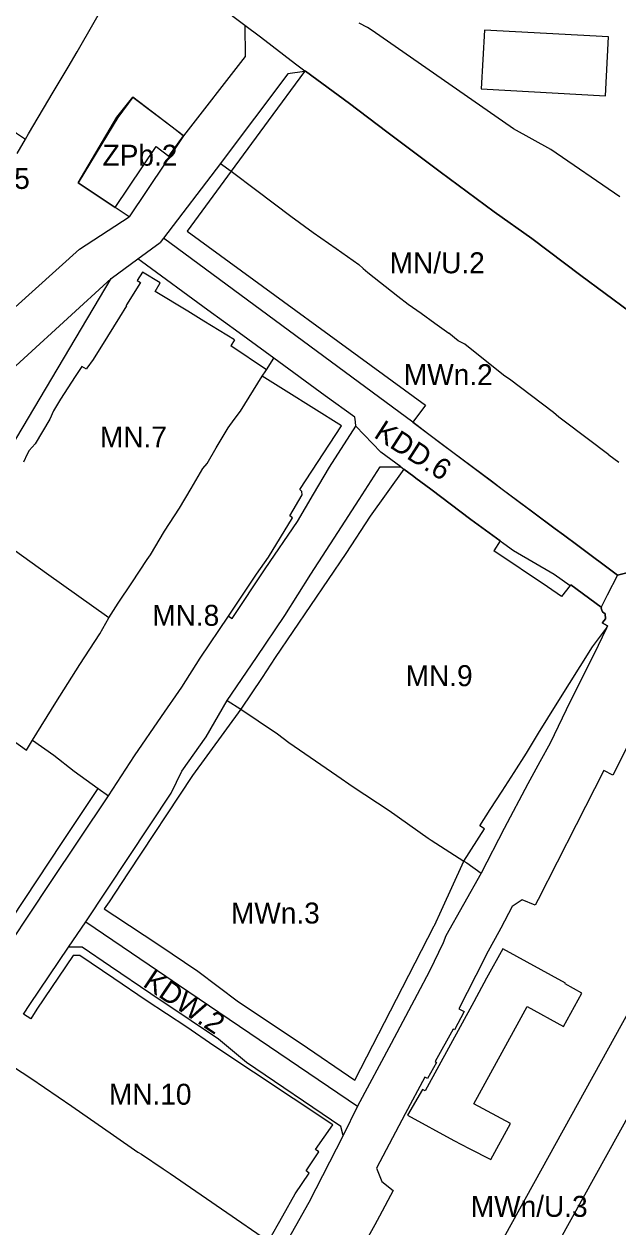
# Model space of a CAD drawing. Extents: x 7425067 to 7426806, y 5549054 to 5550619.
# Drawn here: x 7425656.7 to 7425798.3, y 5549976.3 to 5550263.3 of the extents above; entities that cross this region are included whole.
import ezdxf

# ---------------------------------------------------------------- set-up
doc = ezdxf.new("R2010")
doc.units = 0
for name, color, linetype in [('LIN_Linia Zabudowy Nieprzekraczalna', 7, 'Continuous'), ('LIN_linia zabudowy obowiązująca', 7, 'Continuous'), ('LIN_linie_rozgraniczajace', 7, 'Continuous'), ('TXT_Oznaczenia_przeznaczen', 7, 'Continuous')]:
    doc.layers.add(name, color=color, linetype=linetype)

msp = doc.modelspace()

# ---------------------------------------------------------------- linework, layer by layer
at = {"layer": 'LIN_Linia Zabudowy Nieprzekraczalna'}
for points in [[(7425723.6504, 5550252.1479), (7425723.5322, 5550251.9866), (7425714.88, 5550240.18), (7425706.0572, 5550228.1406), (7425695.5679, 5550213.8271)], [(7425734.29, 5550244.29), (7425723.8133, 5550252.0277), (7425723.6504, 5550252.1479)], [(7425643.3462, 5550245.0982), (7425649, 5550241.7939), (7425649.9122, 5550241.0902), (7425648.76, 5550239.42), (7425652.55, 5550236.62), (7425653.6759, 5550238.1865), (7425654.8959, 5550237.2454), (7425657.0714, 5550235.8304)], [(7425743.15, 5550237.6), (7425734.29, 5550244.29)], [(7425755.89, 5550227.99), (7425743.15, 5550237.6)], [(7425768.78, 5550218.5), (7425755.89, 5550227.99)], [(7425777.76, 5550212.12), (7425768.78, 5550218.5)], [(7425695.5679, 5550213.8271), (7425752.4319, 5550172.3811)], [(7425789.46, 5550203.32), (7425777.76, 5550212.12)], [(7425706.8644, 5550187.9015), (7425699.57, 5550192.42), (7425695.72, 5550194.78), (7425687.9499, 5550199.5099), (7425689.17, 5550201.51), (7425684.95, 5550204.08), (7425683.7, 5550202.1), (7425684.5, 5550201.61), (7425681.13, 5550196.26), (7425681.05, 5550196.08), (7425681.12, 5550196.04), (7425679.5, 5550193.35), (7425676.58, 5550188.74), (7425673.17, 5550183.27), (7425671.68, 5550181.22), (7425671.62, 5550180.97), (7425670.46, 5550181.59), (7425670.16, 5550181.12), (7425668.88, 5550179.16), (7425665.37, 5550173.81), (7425664.22, 5550171.78), (7425663.75, 5550171.01), (7425662.83, 5550169.03), (7425659.36, 5550163.15), (7425657.94, 5550161.51), (7425657.44, 5550160.64), (7425656.55, 5550158.74)], [(7425801.06, 5550194.69), (7425789.46, 5550203.32)], [(7425706.8644, 5550187.9015), (7425705.9808, 5550186.4867)], [(7425713.4587, 5550179.2567), (7425714.3429, 5550180.5794), (7425714.4852, 5550180.8012), (7425705.9808, 5550186.4867)], [(7425732.4116, 5550167.4042), (7425719.21, 5550175.66), (7425713.4971, 5550179.2327), (7425713.4587, 5550179.2567)], [(7425752.4319, 5550172.3811), (7425749.37, 5550168.28)], [(7425705.41, 5550121.99), (7425712.1, 5550132.04), (7425714.96, 5550136.08), (7425720.73, 5550145.49), (7425720.05, 5550145.93), (7425723.04, 5550150.95), (7425722.94, 5550151.72), (7425722.43, 5550152.21), (7425732.4116, 5550167.4042)], [(7425749.37, 5550168.28), (7425768.13, 5550154.2), (7425783.3417, 5550142.8577), (7425785.27, 5550141.43), (7425788.73, 5550138.84)], [(7425770.22, 5550139.98), (7425763.24, 5550145.09), (7425753.66, 5550152.34), (7425750.1, 5550154.975), (7425749.6492, 5550155.3088), (7425747.2699, 5550157.0699), (7425739.22, 5550145.88), (7425733.43, 5550136.96), (7425716.59, 5550112.19), (7425713.48, 5550107.41), (7425708.37, 5550099.83)], [(7425788.73, 5550138.84), (7425798.17, 5550131.83), (7425800.74, 5550132.42), (7425807.33, 5550144.23)], [(7425770.22, 5550139.98), (7425768.6957, 5550137.5981)], [(7425786.8862, 5550129.3024), (7425784.84, 5550126.74), (7425781.45, 5550129.02), (7425768.6957, 5550137.5981)], [(7425783.79, 5550101.26), (7425792.24, 5550114.66), (7425795.54, 5550119.18), (7425795.77, 5550119.74), (7425794.51, 5550120.43), (7425794.65, 5550120.6), (7425795.31, 5550121.41), (7425795.25, 5550122.55), (7425794.6136, 5550123.0868), (7425794.3085, 5550123.8074), (7425794.47, 5550124.03), (7425794.2765, 5550124.1713), (7425787.02, 5550129.47), (7425786.8862, 5550129.3024)], [(7425676.81, 5550079.14), (7425683.08, 5550088.67), (7425689.48, 5550098.09), (7425694.29, 5550105.04), (7425698.72, 5550111.96), (7425705.41, 5550121.99)], [(7425708.37, 5550099.83), (7425696.8865, 5550083.998), (7425681.5412, 5550060.8203)], [(7425765.3724, 5550071.9813), (7425767.85, 5550075.92), (7425770.7, 5550080.3), (7425773.57, 5550084.73), (7425776.44, 5550089.34), (7425779.37, 5550094.1), (7425783.79, 5550101.26)], [(7425665.8055, 5550068.0549), (7425674.3852, 5550080.8809), (7425676.81, 5550079.14)], [(7425761.54, 5550063.58), (7425766.5, 5550071.26), (7425765.3724, 5550071.9813)], [(7425641.7634, 5550031.6816), (7425665.8055, 5550068.0549)], [(7425754.4765, 5550048.1318), (7425754.5355, 5550048.2464), (7425756.2124, 5550051.8896), (7425761.54, 5550063.58)], [(7425681.5412, 5550060.8203), (7425681.5256, 5550060.7966), (7425676.9637, 5550053.8685), (7425675.8274, 5550052.204), (7425678.3491, 5550050.5184), (7425688.8582, 5550043.5856)], [(7425735.5402, 5550011.2981), (7425746.9041, 5550033.4238), (7425754.4765, 5550048.1318)], [(7425688.8582, 5550043.5856), (7425698.1686, 5550037.3516), (7425707.8545, 5550030.0447), (7425722.7668, 5550020.0965), (7425735.5402, 5550011.2981)], [(7425669.979, 5550041.0643), (7425668.3823, 5550041.0497), (7425659.7796, 5550028.2387), (7425658.2986, 5550025.9526), (7425656.62, 5550027.04)], [(7425730.2813, 5550000.6279), (7425701.99, 5550019.54), (7425695.54, 5550023.97), (7425685.81, 5550030.33), (7425678.11, 5550035.55), (7425669.979, 5550041.0643)], [(7425688.8399, 5549929.4585), (7425691.2009, 5549933.3935), (7425702.6055, 5549951.9648), (7425702.86, 5549951.8), (7425709.48, 5549963.44), (7425710.7848, 5549965.653), (7425714.2539, 5549971.5633), (7425714.9902, 5549972.8797), (7425718.3675, 5549978.9183), (7425721.36, 5549984.23), (7425724.68, 5549989.11), (7425723.92, 5549989.66), (7425727.01, 5549994.19), (7425726.17, 5549994.77), (7425730.2813, 5550000.6279)]]:
    msp.add_lwpolyline(points, dxfattribs=at)
at = {"layer": 'LIN_linia zabudowy obowiązująca'}
for points in [[(7425766.4505, 5550261.8233), (7425765.6807, 5550247.8164), (7425795.28, 5550246.18), (7425796.05, 5550260.2), (7425766.4505, 5550261.8233)], [(7425678.4113, 5550219.483), (7425688.2005, 5550234.0314), (7425691.22, 5550231.75), (7425694.75, 5550236.6), (7425682.62, 5550245.86), (7425679.03, 5550240.96), (7425669.6, 5550225.38), (7425678.4113, 5550219.483)], [(7425827.66, 5550076.24), (7425771.07, 5549973.79)], [(7425771.07, 5549973.79), (7425781.44, 5549967.75), (7425838.25, 5550070.38), (7425827.66, 5550076.24)], [(7425770.81, 5550042.66), (7425766.98, 5550035.63), (7425763.9298, 5550030.0314), (7425752.3372, 5550008.753)], [(7425789.7, 5550032.1), (7425785.68, 5550034.31), (7425785.78, 5550034.49), (7425770.81, 5550042.66)], [(7425767.9516, 5549992.377), (7425772.6827, 5550001.0181), (7425763.9256, 5550005.7011), (7425774.7312, 5550025.4086), (7425776.64, 5550028.89), (7425785.32, 5550024.1), (7425789.7, 5550032.1)], [(7425752.3372, 5550008.753), (7425751.67, 5550009.12), (7425748.1216, 5550002.9402)], [(7425748.1216, 5550002.9402), (7425759.1331, 5549996.9604), (7425762.8, 5549994.98), (7425767.9516, 5549992.377)]]:
    msp.add_lwpolyline(points, dxfattribs=at)
at = {"layer": 'LIN_linie_rozgraniczajace'}
for points in [[(7425669.35, 5550256.66), (7425681.8566, 5550278.5552), (7425683.71, 5550281.8)], [(7425698.09, 5550271.56), (7425709.34, 5550263.01)], [(7425738.59, 5550262.44), (7425736.62, 5550263.51)], [(7425709.34, 5550263.01), (7425709.449, 5550255.5422)], [(7425709.34, 5550263.01), (7425713.11, 5550260.26)], [(7425713.11, 5550260.26), (7425721.4, 5550253.81)], [(7425739.71, 5550261.77), (7425738.59, 5550262.44)], [(7425773.39, 5550238.26), (7425739.71, 5550261.77)], [(7425667.19, 5550252.99), (7425669.35, 5550256.66)], [(7425709.449, 5550255.5422), (7425694.75, 5550236.6)], [(7425663.67, 5550247.03), (7425667.19, 5550252.99)], [(7425723.8133, 5550252.0277), (7425723.5322, 5550251.9866), (7425719.5973, 5550251.4119)], [(7425721.4, 5550253.81), (7425723.6504, 5550252.1479), (7425723.8133, 5550252.0277), (7425734.29, 5550244.29)], [(7425719.5973, 5550251.4119), (7425703.69, 5550230.25)], [(7425657.79, 5550237.05), (7425663.67, 5550247.03)], [(7425681.73, 5550217.25), (7425678.4113, 5550219.483), (7425669.6, 5550225.38), (7425678.82, 5550241.04), (7425682.62, 5550245.86), (7425692.37, 5550238.55), (7425694.75, 5550236.6)], [(7425734.29, 5550244.29), (7425743.15, 5550237.6)], [(7425743.15, 5550237.6), (7425755.89, 5550227.99)], [(7425782.29, 5550233.35), (7425773.39, 5550238.26)], [(7425655.04, 5550232.38), (7425657.0714, 5550235.8304), (7425657.79, 5550237.05)], [(7425694.75, 5550236.6), (7425681.73, 5550217.25)], [(7425798.69, 5550222.07), (7425782.29, 5550233.35)], [(7425703.5262, 5550230.0342), (7425689.9613, 5550212.1623)], [(7425703.69, 5550230.25), (7425703.5262, 5550230.0342)], [(7425703.5262, 5550230.0342), (7425706.0572, 5550228.1406), (7425712.18, 5550223.56)], [(7425755.89, 5550227.99), (7425768.78, 5550218.5)], [(7425712.18, 5550223.56), (7425720.285, 5550217.44)], [(7425669.9439, 5550209.5582), (7425681.73, 5550217.25)], [(7425720.285, 5550217.44), (7425725.65, 5550213.56)], [(7425768.78, 5550218.5), (7425777.76, 5550212.12)], [(7425689.9613, 5550212.1623), (7425689.1831, 5550211.137)], [(7425734.85, 5550179.05), (7425689.9613, 5550212.1623)], [(7425725.65, 5550213.56), (7425731.09, 5550209.725)], [(7425777.76, 5550212.12), (7425789.46, 5550203.32)], [(7425638.3977, 5550181.1426), (7425669.9439, 5550209.5582)], [(7425683.8442, 5550207.2287), (7425689.1831, 5550211.137)], [(7425731.09, 5550209.725), (7425736.53, 5550205.89)], [(7425677.4704, 5550202.5629), (7425683.8442, 5550207.2287)], [(7425684.68, 5550206.6), (7425683.8442, 5550207.2287)], [(7425700.56, 5550195.02), (7425684.68, 5550206.6)], [(7425736.53, 5550205.89), (7425737.58, 5550204.93)], [(7425737.58, 5550204.93), (7425738.63, 5550203.97)], [(7425738.63, 5550203.97), (7425745.8, 5550198.34)], [(7425789.46, 5550203.32), (7425801.06, 5550194.69)], [(7425625.3385, 5550154.8249), (7425677.4704, 5550202.5629)], [(7425643.57, 5550145.47), (7425677.4704, 5550202.5629)], [(7425745.8, 5550198.34), (7425748.3, 5550196.42)], [(7425707.95, 5550189.64), (7425700.56, 5550195.02)], [(7425748.3, 5550196.42), (7425751.35, 5550194.29)], [(7425751.35, 5550194.29), (7425754.65, 5550191.895)], [(7425754.65, 5550191.895), (7425757.95, 5550189.5)], [(7425716.24, 5550183.6), (7425707.95, 5550189.64)], [(7425760.17, 5550187.7), (7425757.95, 5550189.5)], [(7425761.77, 5550186.9), (7425760.17, 5550187.7)], [(7425769.83, 5550180.47), (7425761.77, 5550186.9)], [(7425708.27, 5550170.91), (7425713.4971, 5550179.2327), (7425714.3429, 5550180.5794), (7425714.4852, 5550180.8012), (7425716.24, 5550183.6)], [(7425728.525, 5550174.62), (7425716.24, 5550183.6)], [(7425771.35, 5550179.29), (7425769.83, 5550180.47)], [(7425744.57, 5550171.88), (7425734.85, 5550179.05)], [(7425772.4, 5550178.54), (7425771.35, 5550179.29)], [(7425782.94, 5550170.62), (7425772.4, 5550178.54)], [(7425735.5636, 5550169.4749), (7425728.525, 5550174.62)], [(7425749.37, 5550168.28), (7425744.57, 5550171.88)], [(7425705.39, 5550166.91), (7425706.83, 5550168.91)], [(7425706.83, 5550168.91), (7425708.27, 5550170.91)], [(7425735.6875, 5550168.3768), (7425735.5636, 5550169.4749)], [(7425784.16, 5550169.51), (7425782.94, 5550170.62)], [(7425785.42, 5550168.57), (7425784.16, 5550169.51)], [(7425796.12, 5550160.52), (7425785.42, 5550168.57)], [(7425703.935, 5550164.545), (7425705.39, 5550166.91)], [(7425729.56, 5550157.6), (7425735.8, 5550167.38)], [(7425735.8, 5550167.38), (7425735.6875, 5550168.3768)], [(7425741.74, 5550161.16), (7425735.8, 5550167.38)], [(7425752.905, 5550165.585), (7425749.37, 5550168.28)], [(7425756.44, 5550162.89), (7425752.905, 5550165.585)], [(7425702.48, 5550162.18), (7425703.935, 5550164.545)], [(7425768.13, 5550154.2), (7425756.44, 5550162.89)], [(7425700.36, 5550158.44), (7425702.48, 5550162.18)], [(7425746.54, 5550157.61), (7425741.74, 5550161.16)], [(7425796.12, 5550160.52), (7425798.48, 5550158.74)], [(7425696.58, 5550152.46), (7425699.36, 5550157.27)], [(7425699.36, 5550157.27), (7425700.36, 5550158.44)], [(7425725.715, 5550151.12), (7425729.56, 5550157.6)], [(7425736.565, 5550149.815), (7425741.6, 5550157.66)], [(7425741.6, 5550157.66), (7425746.54, 5550157.61)], [(7425746.54, 5550157.61), (7425747.2699, 5550157.0699), (7425749.6492, 5550155.3088), (7425750.1, 5550154.975)], [(7425750.1, 5550154.975), (7425753.66, 5550152.34)], [(7425770.71, 5550152.21), (7425768.13, 5550154.2)], [(7425693.74, 5550147.79), (7425696.58, 5550152.46)], [(7425753.66, 5550152.34), (7425763.24, 5550145.09)], [(7425777.99, 5550146.82), (7425770.71, 5550152.21)], [(7425721.87, 5550144.64), (7425725.715, 5550151.12)], [(7425731.53, 5550141.97), (7425736.565, 5550149.815)], [(7425690.175, 5550142.3), (7425693.74, 5550147.79)], [(7425785.27, 5550141.43), (7425783.3417, 5550142.8577), (7425777.99, 5550146.82)], [(7425714.2, 5550133.34), (7425721.87, 5550144.64)], [(7425763.24, 5550145.09), (7425770.22, 5550139.98)], [(7425662.1, 5550132.23), (7425648.66, 5550141.83)], [(7425686.87, 5550136.67), (7425690.175, 5550142.3)], [(7425725.1, 5550132.01), (7425731.53, 5550141.97)], [(7425770.22, 5550139.98), (7425771.1, 5550139.35)], [(7425788.73, 5550138.84), (7425785.27, 5550141.43)], [(7425771.1, 5550139.35), (7425773.41, 5550137.69)], [(7425773.41, 5550137.69), (7425783.04, 5550132.04)], [(7425798.17, 5550131.83), (7425788.73, 5550138.84)], [(7425682.39, 5550129.95), (7425686.02, 5550135.5)], [(7425686.02, 5550135.5), (7425686.87, 5550136.67)], [(7425676.92, 5550121.64), (7425662.1, 5550132.23)], [(7425706.31, 5550121.49), (7425714.2, 5550133.34)], [(7425718.9, 5550122.19), (7425725.1, 5550132.01)], [(7425783.04, 5550132.04), (7425786.8862, 5550129.3024)], [(7425798.17, 5550131.83), (7425795.73, 5550127.04)], [(7425800.74, 5550132.42), (7425798.17, 5550131.83)], [(7425679.14, 5550125.14), (7425682.39, 5550129.95)], [(7425786.8862, 5550129.3024), (7425787.02, 5550129.47), (7425794.2765, 5550124.1713), (7425794.47, 5550124.03), (7425794.3085, 5550123.8074), (7425794.6136, 5550123.0868), (7425795.25, 5550122.55), (7425795.31, 5550121.41), (7425794.65, 5550120.6), (7425794.51, 5550120.43)], [(7425795.73, 5550127.04), (7425794.2765, 5550124.1713)], [(7425676.92, 5550121.64), (7425679.14, 5550125.14)], [(7425674.77, 5550117.84), (7425676.92, 5550121.64)], [(7425698.72, 5550111.96), (7425705.41, 5550121.99)], [(7425705.41, 5550121.99), (7425706.31, 5550121.49)], [(7425712.09, 5550112.16), (7425718.9, 5550122.19)], [(7425795.77, 5550119.74), (7425795.54, 5550119.18), (7425792.56, 5550112.88)], [(7425794.51, 5550120.43), (7425795.77, 5550119.74)], [(7425669.98, 5550110.47), (7425674.77, 5550117.84)], [(7425694.29, 5550105.04), (7425698.72, 5550111.96)], [(7425705.1471, 5550101.8757), (7425712.09, 5550112.16)], [(7425792.56, 5550112.88), (7425786.89, 5550101.63)], [(7425664.32, 5550101.4), (7425669.98, 5550110.47)], [(7425689.48, 5550098.09), (7425694.29, 5550105.04)], [(7425658.73, 5550092.43), (7425664.32, 5550101.4)], [(7425700.1, 5550093.245), (7425705.1471, 5550101.8757)], [(7425705.1471, 5550101.8757), (7425708.37, 5550099.83)], [(7425708.37, 5550099.83), (7425712.48, 5550097.06)], [(7425786.89, 5550101.63), (7425782.12, 5550091.72)], [(7425646.98, 5550097.47), (7425657.32, 5550090.05)], [(7425683.08, 5550088.67), (7425689.48, 5550098.09)], [(7425712.48, 5550097.06), (7425717.11, 5550093.93)], [(7425717.11, 5550093.93), (7425719.86, 5550091.88)], [(7425657.32, 5550090.05), (7425658.025, 5550091.24)], [(7425658.025, 5550091.24), (7425658.73, 5550092.43)], [(7425658.73, 5550092.43), (7425663.8, 5550088.89)], [(7425694.34, 5550085.07), (7425700.1, 5550093.245)], [(7425719.86, 5550091.88), (7425731.3, 5550084.03)], [(7425782.12, 5550091.72), (7425779.62, 5550087.25)], [(7425800.705, 5550091.3047), (7425797.03, 5550084.0798)], [(7425663.8, 5550088.89), (7425668.62, 5550085.02)], [(7425676.81, 5550079.14), (7425683.08, 5550088.67)], [(7425779.62, 5550087.25), (7425776.82, 5550082.01)], [(7425668.62, 5550085.02), (7425674.3852, 5550080.8809), (7425676.81, 5550079.14)], [(7425691.78, 5550079.79), (7425694.34, 5550085.07)], [(7425731.3, 5550084.03), (7425735.16, 5550081.3)], [(7425794.9029, 5550085.1617), (7425788.32, 5550072.22)], [(7425797.03, 5550084.0798), (7425794.9029, 5550085.1617)], [(7425681.605, 5550064.44), (7425691.78, 5550079.79)], [(7425735.16, 5550081.3), (7425743.76, 5550075.68)], [(7425776.82, 5550082.01), (7425771.15, 5550071.35)], [(7425662.84, 5550058.21), (7425676.81, 5550079.14)], [(7425743.76, 5550075.68), (7425753.07, 5550069.05)], [(7425771.15, 5550071.35), (7425765.67, 5550060.69)], [(7425788.32, 5550072.22), (7425779.24, 5550054.4)], [(7425753.07, 5550069.05), (7425753.79, 5550068.57)], [(7425753.79, 5550068.57), (7425761.54, 5550063.58)], [(7425671.43, 5550049.09), (7425681.605, 5550064.44)], [(7425761.54, 5550063.58), (7425762.23, 5550063.14)], [(7425762.23, 5550063.14), (7425765.67, 5550060.69)], [(7425765.67, 5550060.69), (7425757.27, 5550045.74)], [(7425648.87, 5550037.28), (7425662.84, 5550058.21)], [(7425775.46, 5550054.32), (7425773.025, 5550052.78)], [(7425778.57, 5550053.06), (7425775.46, 5550054.32)], [(7425779.24, 5550054.4), (7425778.57, 5550053.06)], [(7425773.025, 5550052.78), (7425770.36, 5550047.58)], [(7425667.31, 5550043.04), (7425671.43, 5550049.09)], [(7425671.43, 5550049.09), (7425686.53, 5550038.81)], [(7425757.27, 5550045.74), (7425756.58, 5550044.1)], [(7425769.89, 5550046.72), (7425767.36, 5550042.09)], [(7425770.36, 5550047.58), (7425769.89, 5550046.72)], [(7425658.11, 5550029.34), (7425667.31, 5550043.04)], [(7425670.59, 5550043.07), (7425667.31, 5550043.04)], [(7425677.35, 5550038.44), (7425670.59, 5550043.07)], [(7425756.58, 5550044.1), (7425753.37, 5550037.35)], [(7425767.36, 5550042.09), (7425764.41, 5550036.28)], [(7425686.92, 5550031.89), (7425677.35, 5550038.44)], [(7425686.53, 5550038.81), (7425690.49, 5550036.11)], [(7425753.37, 5550037.35), (7425750.415, 5550031.78)], [(7425690.49, 5550036.11), (7425693.55, 5550034.03)], [(7425693.55, 5550034.03), (7425710.56, 5550022.52)], [(7425764.41, 5550036.28), (7425762.33, 5550032.22)], [(7425696.55, 5550025.46), (7425686.92, 5550031.89)], [(7425750.415, 5550031.78), (7425744.215, 5550020.055)], [(7425762.33, 5550032.22), (7425760.36, 5550028.35)], [(7425656.62, 5550027.04), (7425658.11, 5550029.34)], [(7425760.36, 5550028.35), (7425761.61, 5550027.68)], [(7425703.04, 5550021.12), (7425696.55, 5550025.46)], [(7425761.61, 5550027.68), (7425759.32, 5550023.31)], [(7425710.56, 5550022.52), (7425736.18, 5550005.13)], [(7425758.97, 5550023.49), (7425754.69, 5550015.8)], [(7425759.32, 5550023.31), (7425758.97, 5550023.49)], [(7425709.75, 5550015.56), (7425703.04, 5550021.12)], [(7425744.215, 5550020.055), (7425736.18, 5550005.13)], [(7425649.98, 5550017.22), (7425658.32, 5550011.79)], [(7425732.25, 5550000.28), (7425709.75, 5550015.56)], [(7425755.04, 5550015.51), (7425752.87, 5550011.74)], [(7425754.69, 5550015.8), (7425755.04, 5550015.51)], [(7425658.32, 5550011.79), (7425668.12, 5550005.08)], [(7425752.235, 5550012.025), (7425747.545, 5550003.255)], [(7425752.87, 5550011.74), (7425752.235, 5550012.025)], [(7425668.12, 5550005.08), (7425678.07, 5549998.16)], [(7425736.18, 5550005.13), (7425732.79, 5549998.15)], [(7425747.545, 5550003.255), (7425740.7378, 5549990.3615)], [(7425732.79, 5549998.15), (7425732.25, 5550000.28)], [(7425678.07, 5549998.16), (7425683.87, 5549994.18)], [(7425732.79, 5549998.15), (7425724.58, 5549982.13)], [(7425683.87, 5549994.18), (7425684.68, 5549993.63)], [(7425684.68, 5549993.63), (7425689.87, 5549990.15)], [(7425689.87, 5549990.15), (7425691.53, 5549989.04)], [(7425691.53, 5549989.04), (7425705.05, 5549979.74)], [(7425740.7378, 5549990.3615), (7425742.0007, 5549987.1254)], [(7425744.68, 5549985.03), (7425741.44, 5549978.84)], [(7425742.0007, 5549987.1254), (7425744.68, 5549985.03)], [(7425724.58, 5549982.13), (7425718.26, 5549970.81)], [(7425705.05, 5549979.74), (7425714.5, 5549973.19)], [(7425740.32, 5549976.83), (7425729.34, 5549957.05)], [(7425741.44, 5549978.84), (7425740.32, 5549976.83)]]:
    msp.add_lwpolyline(points, dxfattribs=at)

# ---------------------------------------------------------------- texts
at = {"layer": 'TXT_Oznaczenia_przeznaczen'}
for s, p in [('ZPb.2', (7425675.4305, 5550229.4826)), ('ZP.5', (7425643.9631, 5550223.9449)), ('MN/U.2', (7425743.8716, 5550203.823)), ('MWn.2', (7425747.241, 5550177.1358)), ('MN.7', (7425674.7942, 5550162.2619)), ('MN.8', (7425687.2686, 5550119.7142)), ('MN.9', (7425747.6658, 5550105.3191)), ('MWn.3', (7425706.0252, 5550048.6923)), ('MN.10', (7425676.9359, 5550005.4595)), ('MWn/U.3', (7425763.1959, 5549978.7132))]:
    msp.add_text(s, height=5, dxfattribs=at).set_placement(p)
for s, rotation, p in [('KDD.6', 327.227507, (7425739.8452, 5550164.8283)), ('KDW.2', 326.030476, (7425684.7672, 5550033.8721))]:
    msp.add_text(s, height=5, rotation=rotation, dxfattribs=at).set_placement(p)

doc.saveas('drawing.dxf')
